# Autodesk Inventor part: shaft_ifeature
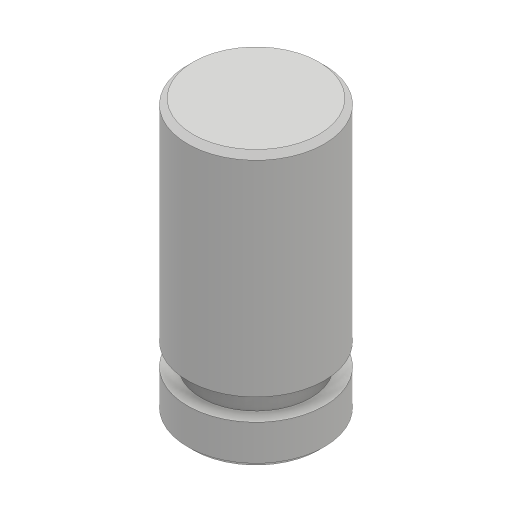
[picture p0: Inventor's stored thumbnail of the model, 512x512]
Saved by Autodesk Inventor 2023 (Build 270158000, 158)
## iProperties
Created: 2016-08
Part Number: shaft_ifeature
Material: Generic
Document SubType Name: Modeling
Designer: Sandeep
Density: 1 g/cm^3
Appearance: Default
Author: Sandeep
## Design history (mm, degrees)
sketch "Sketch1"
  geometry: C1 r 25 at (0, 0); 1 further point
  constraints: 1 centre point, 1 coincident
  dimensions: "d0" = 50 diameter of C1
extrude "Extrusion1" new body sketch "Sketch1" distance "d1" = 100; taper "d2" = 0 deg
chamfer "Chamfer1" distance "d3" = 2; stored, may be unused: second distance "d4" = 2, angle "d5" = 45 deg
chamfer "Chamfer2" distance "d6" = 2; stored, may be unused: second distance "d7" = 2, angle "d8" = 45 deg
sketch "Sketch3"
  geometry: L1 (-25, 23)-(-20, 23); L2 (-20, 23)-(-20, 15); L3 (-20, 15)-(-25, 15); L4 (-25, 15)-(-25, 23); L5 (0, 0)-(0, 35)
  constraints: 10 end point, 2 parallel, 1 horizontal, 1 perpendicular, 1 vertical
  dimensions: "d13" = 8 distance of L3.end L1.start; "d14" = 25 distance between parallel lines of L4 L5; "d15" = 20 distance between parallel lines of L2 L5; "d17" = 15 distance from line of L3 L5.start
revolve "Revolution2" sketch "Sketch3" stored, may be unused: angle "d18" = 90 deg
body "Solid1"
